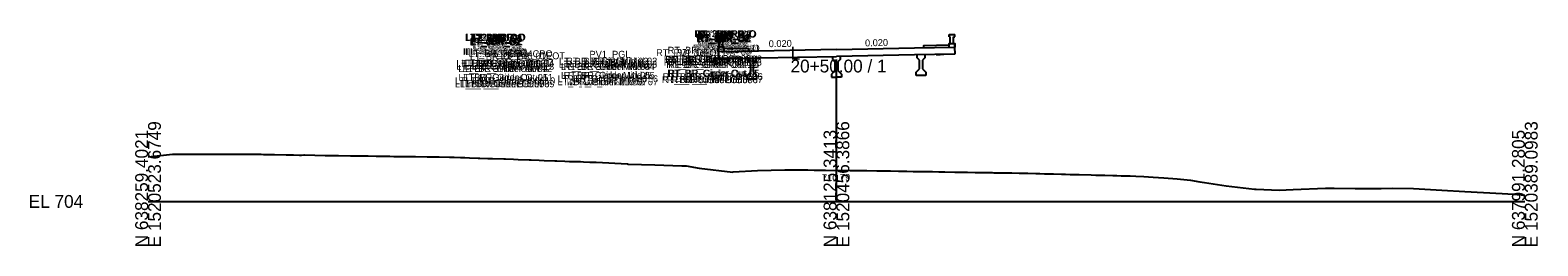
# Model space of a CAD drawing. Extents: x -26 to 3903, y -10 to 9531.
# Drawn here: x 974.3 to 1302.8, y 490.3 to 537.4 of the extents above; entities that cross this region are included whole.
import ezdxf

# ---------------------------------------------------------------- set-up
doc = ezdxf.new("R2010")
doc.units = 0
for name, color, linetype in [('Default', 7, 'Continuous'), ('Exist Cross Section Cell', 7, 'Continuous'), ('Exist XS Center Line Elevation Label', 7, 'Continuous'), ('Exist XS Ground Line', 7, 'Continuous'), ('Prop CMT Conc Surface', 7, 'Continuous'), ('Prop XS Conc Monolithic Island', 7, 'Continuous'), ('Prop XS Finish Grade', 7, 'Continuous'), ('Prop XS SE Text', 7, 'Continuous')]:
    doc.layers.add(name, color=color, linetype=linetype)

msp = doc.modelspace()

# ---------------------------------------------------------------- linework, layer by layer
at = {"layer": 'Exist Cross Section Cell'}
for p, q in [((1150, 500), (1150, 530.92)), ((1000, 500), (1150, 500)), ((1150, 500), (1300, 500))]:
    msp.add_line(p, q, dxfattribs=at)
at = {"layer": 'Exist XS Ground Line'}
msp.add_lwpolyline([(1000, 509.74), (1005.36, 510.31), (1005.69, 510.31), (1005.88, 510.31), (1013.36, 510.27), (1017.46, 510.28), (1023.73, 510.28), (1024.67, 510.27), (1025.12, 510.25), (1027.43, 510.2), (1027.49, 510.2), (1027.53, 510.2), (1030.06, 510.17), (1030.31, 510.16), (1030.72, 510.17), (1031.72, 510.15), (1033.01, 510.12), (1033.45, 510.12), (1033.97, 510.13), (1034.06, 510.13), (1036.32, 510.09), (1038.58, 510.04), (1038.66, 510.04), (1038.7, 510.04), (1038.82, 510.03), (1041.5, 509.99), (1044.12, 509.96), (1044.31, 509.95), (1046.11, 509.93), (1047.09, 509.92), (1047.97, 509.91), (1049.73, 509.89), (1049.84, 509.88), (1049.89, 509.88), (1050.05, 509.88), (1052.7, 509.84), (1053.56, 509.83), (1055.26, 509.8), (1055.49, 509.8), (1057.28, 509.77), (1058.28, 509.76), (1060.81, 509.72), (1060.98, 509.72), (1061.09, 509.72), (1061.27, 509.72), (1063.45, 509.69), (1065.65, 509.67), (1065.9, 509.66), (1066.26, 509.66), (1066.31, 509.65), (1066.68, 509.62), (1068.1, 509.59), (1069.03, 509.56), (1070.04, 509.52), (1071.93, 509.46), (1072.28, 509.44), (1074.03, 509.39), (1075.07, 509.35), (1077.49, 509.26), (1077.87, 509.25), (1079.62, 509.19), (1080.67, 509.15), (1083.07, 509.06), (1083.47, 509.05), (1085.21, 508.98), (1086.28, 508.94), (1088.67, 508.86), (1088.93, 508.85), (1089.07, 508.84), (1090.79, 508.78), (1091.86, 508.74), (1094.2, 508.67), (1094.88, 508.64), (1096.3, 508.59), (1096.68, 508.58), (1097.61, 508.55), (1104.44, 508.16), (1104.63, 508.15), (1110.46, 507.99), (1116.29, 507.79), (1116.67, 507.77), (1117.26, 507.76), (1120.12, 507.27), (1127.44, 506.41), (1127.47, 506.42), (1127.48, 506.42), (1132.78, 506.73), (1138.76, 506.88), (1143.74, 506.86), (1145.15, 506.85), (1147.62, 506.82), (1153.01, 506.76), (1156.6, 506.73), (1158.82, 506.7), (1161.02, 506.66), (1161.37, 506.66), (1161.66, 506.65), (1161.8, 506.65), (1163.5, 506.62), (1164.58, 506.6), (1165.35, 506.58), (1166.74, 506.56), (1167.37, 506.55), (1168, 506.54), (1170.19, 506.5), (1170.9, 506.49), (1172.33, 506.47), (1172.98, 506.46), (1173.63, 506.45), (1175.77, 506.41), (1177.9, 506.37), (1178.58, 506.36), (1180.2, 506.33), (1181.36, 506.31), (1182.07, 506.3), (1183.46, 506.28), (1183.93, 506.27), (1184.32, 506.26), (1185.44, 506.24), (1185.94, 506.24), (1186.2, 506.23), (1187.91, 506.22), (1188.19, 506.21), (1189.82, 506.18), (1191.43, 506.13), (1191.61, 506.13), (1191.74, 506.13), (1193.45, 506.09), (1194.32, 506.06), (1195.33, 506.04), (1197.11, 505.99), (1197.3, 505.99), (1199.04, 505.95), (1199.91, 505.92), (1200.91, 505.9), (1202.71, 505.85), (1202.86, 505.85), (1205.51, 505.78), (1206.49, 505.75), (1208.32, 505.71), (1208.46, 505.7), (1210.2, 505.66), (1211.11, 505.63), (1212.07, 505.6), (1213.9, 505.55), (1213.99, 505.55), (1215.25, 505.51), (1216.98, 505.45), (1219.05, 505.3), (1221.34, 505.12), (1224.25, 504.9), (1227.18, 504.6), (1229.2, 504.24), (1230.2, 504.13), (1234.92, 503.43), (1241.09, 502.65), (1241.47, 502.64), (1246.44, 502.47), (1249.53, 502.63), (1256.55, 502.88), (1258.44, 502.87), (1263.06, 502.83), (1267.74, 502.83), (1268.72, 502.82), (1271.27, 502.87), (1275.77, 502.82), (1281.95, 502.44), (1286.95, 502.17), (1295.08, 501.71), (1297.51, 501.57), (1300, 501.33)], dxfattribs=at)
at = {"layer": 'Prop XS Conc Monolithic Island'}
for p, q in [((1174.53, 535.89), (1174.53, 536.39)), ((1174.53, 536.39), (1175.78, 536.39)), ((1174.78, 535.89), (1174.53, 535.89)), ((1174.78, 534.39), (1174.78, 535.89)), ((1175.53, 534.39), (1175.53, 535.89)), ((1175.53, 535.89), (1175.78, 535.89)), ((1175.78, 535.89), (1175.78, 536.39)), ((1124.22, 534.86), (1124.22, 535.36)), ((1124.22, 535.36), (1125.47, 535.36)), ((1124.47, 534.86), (1124.22, 534.86)), ((1124.22, 532.6), (1124.22, 533.36)), ((1124.22, 533.36), (1124.47, 533.36)), ((1124.47, 533.36), (1124.47, 534.86)), ((1125.22, 533.36), (1125.22, 534.86)), ((1125.22, 534.86), (1125.47, 534.86)), ((1125.47, 533.36), (1125.22, 533.36)), ((1125.47, 534.86), (1125.47, 535.36)), ((1125.47, 532.6), (1125.47, 533.36)), ((1174.53, 533.63), (1174.53, 534.39)), ((1174.53, 534.39), (1174.78, 534.39)), ((1175.78, 534.39), (1175.53, 534.39)), ((1175.78, 533.63), (1175.78, 534.39))]:
    msp.add_line(p, q, dxfattribs=at)
for points in [[(1150, 533.12), (1133, 532.78), (1124.22, 532.6)], [(1124.22, 532.6), (1124.25, 531.1)], [(1126.29, 532.64), (1131, 532.74)], [(1150, 533.12), (1167, 533.46), (1175.78, 533.63)], [(1175.75, 533.66), (1175.78, 532.13)], [(1124.25, 531.1), (1133, 531.28), (1150, 531.62)], [(1128.25, 531.18), (1127.42, 531.17), (1126.58, 531.15)], [(1130.74, 531.23), (1130.74, 530.58)], [(1130.74, 530.58), (1131.24, 530.08)], [(1131.24, 530.08), (1131.24, 528.17)], [(1131.91, 530.08), (1132.41, 530.58)], [(1131.91, 528.17), (1131.91, 530.08)], [(1132.41, 530.58), (1132.41, 531.27)], [(1149.17, 531.6), (1149.17, 530.95)], [(1149.17, 530.95), (1149.67, 530.45)], [(1149.67, 530.45), (1149.67, 528.53)], [(1175.78, 532.13), (1167, 531.96), (1150, 531.62)], [(1150.83, 530.95), (1150.33, 530.45)], [(1150.33, 530.45), (1150.33, 528.53)], [(1150.83, 531.63), (1150.83, 530.95)], [(1167.59, 531.32), (1167.59, 531.97)], [(1168.09, 530.82), (1167.59, 531.32)], [(1168.09, 528.9), (1168.09, 530.82)], [(1169.26, 531.32), (1168.76, 530.82)], [(1168.76, 530.82), (1168.76, 528.9)], [(1169.26, 532), (1169.26, 531.32)], [(1171.75, 532.05), (1172.58, 532.07), (1173.42, 532.09)], [(1131.24, 528.17), (1130.49, 527.42)], [(1130.49, 527.42), (1130.49, 526.75)], [(1130.49, 526.75), (1131.58, 526.75), (1132.66, 526.75)], [(1132.66, 527.42), (1131.91, 528.17)], [(1132.66, 526.75), (1132.66, 527.42)], [(1149.67, 528.53), (1148.92, 527.78)], [(1148.92, 527.78), (1148.92, 527.12)], [(1148.92, 527.12), (1150, 527.12)], [(1151.08, 527.12), (1150, 527.12)], [(1150.33, 528.53), (1151.08, 527.78)], [(1151.08, 527.78), (1151.08, 527.12)], [(1167.34, 528.15), (1168.09, 528.9)], [(1167.34, 527.49), (1167.34, 528.15)], [(1169.51, 527.49), (1168.42, 527.49), (1167.34, 527.49)], [(1168.76, 528.9), (1169.51, 528.15)], [(1169.51, 528.15), (1169.51, 527.49)]]:
    msp.add_lwpolyline(points, dxfattribs=at)
at = {"layer": 'Prop XS Finish Grade'}
for p, q in [((1130.93, 532.74), (1130.93, 533.29)), ((1169.07, 533.5), (1169.07, 534))]:
    msp.add_line(p, q, dxfattribs=at)
for points in [[(1130.93, 532.74), (1130.93, 533.29), (1125.43, 533.35), (1125.43, 533.69), (1124.22, 533.69), (1124.22, 532.6)], [(1169.07, 533.5), (1169.07, 534), (1174.57, 534.11), (1174.57, 534.45), (1175.78, 534.45), (1175.78, 533.63)]]:
    msp.add_lwpolyline(points, dxfattribs=at)

# ---------------------------------------------------------------- texts
at = {"layer": 'Default'}
msp.add_text('-', height=0.0001, dxfattribs=at).set_placement((1000, 500))
at = {"layer": 'Exist Cross Section Cell'}
for s, p in [('L', (1140, 530.92)), ('20+50.00 / 1', (1140, 528.12)), ('EL 704', (974, 498.6))]:
    msp.add_text(s, height=2.8, dxfattribs=at).set_placement(p)
for s, p in [('E 1520523.6749', (1002.8, 490)), ('E 1520456.3866', (1152.8, 490)), ('E 1520389.0983', (1302.8, 490)), ('N 638259.4021', (1000, 490)), ('N 638125.3413', (1150, 490)), ('N 637991.2805', (1300, 490))]:
    msp.add_text(s, height=2.8, rotation=90, dxfattribs=at).set_placement(p)
at = {"layer": 'Exist XS Center Line Elevation Label'}
msp.add_text('710.79', height=1.5, rotation=0.8401, dxfattribs=at).set_placement((1146.88, 504.4))
at = {"layer": 'Prop CMT Conc Surface'}
for s, p in [('LT_5BMRP_O', (1069.03, 534.98)), ('LT_3BMRP_O', (1069.11, 535.07)), ('LT_2BMRP_O', (1069.26, 535.07)), ('LT_0BR_O2', (1070.09, 534.07)), ('LT_2BR_O2', (1070.17, 534.23)), ('LT_1BR_O2', (1070.27, 534.23)), ('LT_0BR_O1', (1070.31, 534.9)), ('LT_2BR_O1', (1070.39, 535.07)), ('LT_6BR_O1', (1070.39, 534.73)), ('LT_3BR_O2', (1070.4, 534.17)), ('LT_1BR_O1', (1070.49, 535.07)), ('LT_4BR_O2', (1070.49, 534.07)), ('LT_3BR_O1', (1070.62, 535.01)), ('LT_7BR_O', (1070.63, 534.73)), ('LT_4BR_O1', (1070.7, 534.9)), ('LT_5BR_O', (1070.94, 534.8)), ('RT_2BMRP_O', (1119.01, 535.83)), ('RT_3BMRP_O', (1119.15, 535.83)), ('RT_5BMRP_O', (1119.24, 535.74)), ('RT_4BR_O2', (1119.44, 534.83)), ('RT_3BR_O2', (1119.52, 534.93)), ('RT_5BR_O2', (1119.52, 534.72)), ('RT_4BR_O1', (1119.66, 535.66)), ('RT_3BR_O1', (1119.74, 535.77)), ('RT_2BR_O2', (1119.75, 534.99)), ('RT_6BR_O2', (1119.75, 534.66)), ('RT_0BR_O2', (1119.84, 534.83)), ('RT_3BR_O', (1119.96, 534.17)), ('RT_2BR_O1', (1119.97, 535.83)), ('RT_6BR_O1', (1119.97, 535.49)), ('RT_1BR_O2', (1120.02, 534.99)), ('RT_2BR_O', (1120.05, 534.16)), ('RT_0BR_O1', (1120.05, 535.66)), ('RT_7BR_O1', (1120.05, 534.66)), ('RT_5BR_O', (1120.06, 535.56)), ('RT_1BR_O1', (1120.23, 535.83)), ('RT_7BR_O', (1120.38, 535.49)), ('LT_6BMRP_O', (1068.63, 531.91)), ('LT_BR_1CPO', (1068.79, 531.91)), ('LT_4BMRP_O', (1069.11, 531.91)), ('LT_1BMRP_O', (1069.44, 531.91)), ('LT_BR_2CPO', (1069.82, 531.91)), ('LT_BR_3CPO', (1069.82, 531.57)), ('LT_BR_02', (1070.15, 530.82)), ('LT_6BR_O2', (1070.17, 533.9)), ('LT_7BR_O1', (1070.31, 533.9)), ('LT_5BR_O2', (1070.4, 533.96)), ('LT_0BR_O', (1070.63, 532.91)), ('LT_6BR_O', (1070.63, 532.66)), ('LT_5BR_O1', (1070.64, 532.42)), ('LT_1BR_O', (1070.81, 533.16)), ('LT_2BR_O', (1070.96, 533.4)), ('LT_3BR_O', (1071.05, 533.41)), ('LT_4BR_O', (1071.05, 532.41)), ('LT_BR_4CPO', (1075.32, 531.46)), ('LT_PV1_OEOT', (1076.8, 531)), ('LT_BR_01', (1077.07, 530.96)), ('PV1_PGL', (1096.2, 531.34)), ('RT_PV1_OEOT', (1110.71, 531.68)), ('RT_BR_4CPO', (1113.23, 532.22)), ('RT_BR_01', (1114.99, 531.72)), ('RT_BR_2CPO', (1118.73, 532.67)), ('RT_BR_3CPO', (1118.73, 532.33)), ('RT_4BMRP_O', (1119.15, 532.67)), ('RT_1BMRP_O', (1119.19, 532.67)), ('RT_6BMRP_O', (1119.63, 532.67)), ('RT_5BR_O1', (1119.73, 533.18)), ('RT_4BR_O', (1119.96, 533.17)), ('RT_BR_1CPO', (1120.12, 532.67)), ('RT_0BR_O', (1120.38, 533.67)), ('RT_6BR_O', (1120.38, 533.42)), ('RT_1BR_O', (1120.56, 533.92)), ('RT_BR_02', (1121.48, 531.85)), ('LT_BR_Girder Out 03', (1067.15, 528.72)), ('LT_BR_Girder Out 02', (1067.17, 529.37)), ('LT_BR_Girder Out 04', (1067.62, 528.22)), ('LT_BR_Girder Out 01', (1068.22, 529.39)), ('LT_BR_Girder Out 12', (1068.52, 528.22)), ('LT_BR_Girder Out 14', (1068.97, 529.4)), ('LT_BR_Girder Out 13', (1068.99, 528.72)), ('LT_BR_06', (1070.11, 529.32)), ('LT_BR_07', (1078.79, 529.5)), ('LT_BR_Girder Mid 03', (1089.5, 529.17)), ('LT_BR_Girder Mid 02', (1089.53, 529.82)), ('LT_BR_Girder Mid 04', (1089.98, 528.67)), ('RT_BR_Girder Mid 04', (1090.56, 528.67)), ('RT_BR_Girder Mid 03', (1091.08, 529.17)), ('RT_BR_Girder Mid 02', (1091.11, 529.85)), ('BR_PGL', (1096.63, 529.84)), ('RT_BR_Girder Out 14', (1112.38, 530.27)), ('RT_BR_Girder Out 13', (1112.4, 529.62)), ('RT_BR_07', (1112.7, 530.18)), ('RT_BR_Girder Out 12', (1112.93, 529.12)), ('RT_BR_Girder Out 01', (1113.3, 530.29)), ('RT_BR_Girder Out 04', (1113.37, 529.12)), ('RT_BR_Girder Out 03', (1113.89, 529.62)), ('RT_BR_Girder Out 02', (1113.92, 530.31)), ('RT_BR_06', (1121.43, 530.35)), ('LT_BR_Girder Out 07', (1066.86, 524.89)), ('LT_BR_Girder Out 06', (1066.88, 525.55)), ('LT_BR_Girder Out 05', (1067.64, 526.3)), ('LT_BR_Girder Out 08', (1067.96, 524.89)), ('LT_BR_Girder Out 11', (1068.74, 526.3)), ('LT_BR_Girder Out 09', (1069.05, 524.89)), ('LT_BR_Girder Out 10', (1069.21, 525.55)), ('LT_BR_Girder Mid 07', (1089.21, 525.34)), ('LT_BR_Girder Mid 06', (1089.24, 526)), ('LT_BR_Girder Mid 05', (1089.99, 526.75)), ('RT_BR_Girder Mid 05', (1090.57, 526.75)), ('RT_BR_Girder Mid 07', (1091.29, 525.34)), ('RT_BR_Girder Mid 06', (1091.31, 526)), ('BR_Girder Mid 08', (1091.77, 525.34)), ('RT_BR_Girder Out 09', (1111.96, 525.79)), ('RT_BR_Girder Out 10', (1112.12, 526.46)), ('RT_BR_Girder Out 08', (1113.04, 525.79)), ('RT_BR_Girder Out 11', (1113.15, 527.21)), ('RT_BR_Girder Out 05', (1113.38, 527.21)), ('RT_BR_Girder Out 07', (1114.1, 525.79)), ('RT_BR_Girder Out 06', (1114.12, 526.46))]:
    msp.add_text(s, height=1.5, dxfattribs=at).set_placement(p)
at = {"layer": 'Prop XS SE Text'}
for p in [(1135.26, 533.63), (1156.24, 533.81)]:
    msp.add_text('0.020', height=1.5, rotation=1.1458, dxfattribs=at).set_placement(p)

doc.saveas('drawing.dxf')
